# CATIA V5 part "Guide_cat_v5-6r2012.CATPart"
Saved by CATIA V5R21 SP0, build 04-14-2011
Part number: Guide
Bounding box of the stored display mesh (mm): x -5 to 5, y -5 to 5, z -25 to 25
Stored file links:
  D:\CATIA V5R21 E-RESOURCES\CATIA-V5R21\catia-v5r21-Tut\c16-catia-v5r21-tut\c16-catia-v5r21-tut03\Guide_cat_v5r21.CATPart
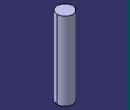
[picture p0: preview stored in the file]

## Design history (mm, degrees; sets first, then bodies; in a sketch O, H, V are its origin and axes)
Body1 (main body)
  Sketch1 on xy-plane, origin (0, 0, 0), H (1, 0, 0), V (0, 1, 0)
    circle A1 centre (0, 0) radius 5
    radius A1 = 5
  Pad1: profile Sketch1, direction (0, 0, 1), length 25, mirrored extent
